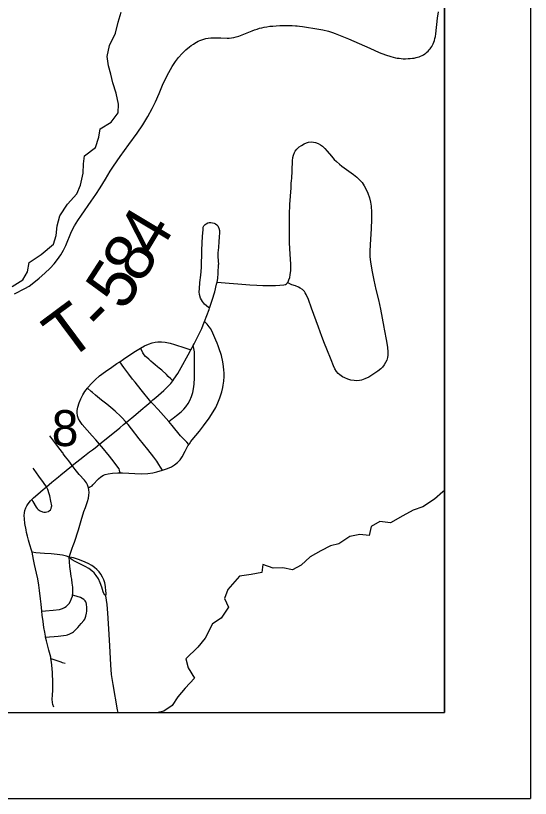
# Model space of a CAD drawing. Extents: x -14196 to 143, y -6096 to 28.
# Drawn here: x 64.404 to 65.003, y 16.799 to 17.71 of the extents above; entities that cross this region are included whole.
import ezdxf

# ---------------------------------------------------------------- set-up
doc = ezdxf.new("R2010")
doc.units = 0
for name, color, linetype in [('GM_X_Corporation', 7, 'Continuous'), ('GM_X_Major_River', 7, 'Continuous'), ('GM_X_Minor_River', 7, 'Continuous'), ('GM_X_Section_Text', 7, 'Continuous'), ('GM_X_Township_Road', 7, 'Continuous'), ('GM_X_Township_Road_Text', 7, 'Continuous'), ('SH_Data', 7, 'Continuous')]:
    doc.layers.add(name, color=color, linetype=linetype)

msp = doc.modelspace()

# ---------------------------------------------------------------- linework, layer by layer
at = {"layer": 'GM_X_Corporation'}
for points in [[(58.10282, 16.89854), (64.90282, 16.89854), (64.90282, 18.72858), (64.42664, 18.73471), (64.36963, 18.73435), (63.68786, 18.74138), (63.08865, 18.75772), (62.54026, 18.77306)], [(62.31172, 16.89854), (64.90282, 16.89854), (64.90282, 18.72858), (64.42664, 18.73471), (64.36963, 18.73435), (63.68786, 18.74138), (63.08865, 18.75772), (62.54026, 18.77306)]]:
    msp.add_lwpolyline(points, dxfattribs=at)
msp.add_lwpolyline([(64.36791, 16.89854), (64.90282, 16.89854), (64.90282, 17.75358), (64.39395, 17.76746)], close=True, dxfattribs=at)
at = {"layer": 'GM_X_Major_River'}
msp.add_lwpolyline([(64.90282, 17.15681), (64.90109, 17.15543), (64.89132, 17.147), (64.87777, 17.13777), (64.86644, 17.13387), (64.85437, 17.12731), (64.84005, 17.11922), (64.82752, 17.12099), (64.81773, 17.11483), (64.81518, 17.10457), (64.80455, 17.10561), (64.79283, 17.10322), (64.78003, 17.09476), (64.77019, 17.09239), (64.75888, 17.0866), (64.74644, 17.07966), (64.73631, 17.07009), (64.72613, 17.06468), (64.71473, 17.06685), (64.70336, 17.06636), (64.69156, 17.07079), (64.69052, 17.06131), (64.67803, 17.0593), (64.66441, 17.05727), (64.65092, 17.04161), (64.64686, 17.03134), (64.65152, 17.02115), (64.64294, 17.00819), (64.63277, 17.00165), (64.62461, 16.98491), (64.616, 16.97459), (64.60174, 16.96082), (64.6045, 16.95062), (64.61184, 16.93857), (64.60097, 16.92673), (64.59273, 16.9168), (64.58602, 16.90651), (64.57623, 16.89998), (64.56973, 16.89854)], dxfattribs=at)
at = {"layer": 'GM_X_Minor_River'}
msp.add_lwpolyline([(64.4, 17.39441), (64.41243, 17.40211), (64.41764, 17.41165), (64.41942, 17.42229), (64.43373, 17.43153), (64.44801, 17.44381), (64.45094, 17.4537), (64.45234, 17.4651), (64.45525, 17.47651), (64.4642, 17.49026), (64.47507, 17.5025), (64.47952, 17.51241), (64.48241, 17.52648), (64.48267, 17.53711), (64.48409, 17.54661), (64.49688, 17.55623), (64.50055, 17.56841), (64.50234, 17.57791), (64.51516, 17.58563), (64.523, 17.59671), (64.52366, 17.60659), (64.52087, 17.61947), (64.51695, 17.63158), (64.51457, 17.64181), (64.51182, 17.65127), (64.51019, 17.66226), (64.51309, 17.67482), (64.52014, 17.68932), (64.52304, 17.70225), (64.52672, 17.71368)], dxfattribs=at)
at = {"layer": 'GM_X_Township_Road'}
for points in [[(64.40255, 17.38586), (64.4147, 17.3921), (64.4195, 17.39495), (64.42506, 17.39891), (64.43132, 17.40401), (64.4378, 17.40981), (64.44396, 17.41594), (64.44856, 17.42098), (64.45247, 17.4258), (64.45442, 17.42848), (64.45644, 17.43136), (64.45803, 17.43382), (64.45962, 17.43669), (64.46233, 17.44227), (64.46906, 17.4583), (64.47243, 17.46494), (64.47627, 17.47132), (64.48042, 17.47749), (64.49183, 17.4937), (64.4971, 17.50137), (64.50211, 17.50922), (64.50825, 17.51929), (64.51398, 17.52889), (64.51769, 17.53462), (64.52549, 17.54584), (64.53572, 17.55992), (64.54517, 17.57301), (64.5518, 17.58278), (64.55766, 17.5923), (64.56274, 17.60155), (64.56658, 17.60936), (64.57079, 17.61903), (64.57488, 17.62873), (64.57872, 17.63715), (64.58211, 17.6437), (64.58613, 17.65058), (64.58985, 17.65619), (64.59356, 17.66104), (64.59758, 17.66567), (64.60196, 17.66998), (64.60622, 17.67353), (64.60831, 17.67507), (64.61076, 17.67672), (64.61256, 17.67785), (64.61448, 17.67889), (64.61632, 17.67988), (64.61837, 17.68074), (64.62052, 17.68161), (64.6228, 17.68235), (64.62532, 17.68297), (64.62781, 17.68344), (64.63085, 17.68383), (64.63291, 17.68402), (64.63515, 17.6841), (64.6387, 17.68402), (64.64254, 17.68384), (64.64994, 17.6836), (64.65239, 17.68366), (64.65498, 17.68389), (64.65788, 17.68431), (64.66065, 17.685), (64.66378, 17.686), (64.66737, 17.6874), (64.67119, 17.68896), (64.67508, 17.69055), (64.67915, 17.69221), (64.68198, 17.69326), (64.68498, 17.69419), (64.68759, 17.69499), (64.69032, 17.69565), (64.69327, 17.69628), (64.69637, 17.69686), (64.69968, 17.69733), (64.7031, 17.6977), (64.70702, 17.69801), (64.71112, 17.69818), (64.72098, 17.6983), (64.72557, 17.69826), (64.72941, 17.69805), (64.73161, 17.69789), (64.73408, 17.69764), (64.73784, 17.69715), (64.74234, 17.69641), (64.75218, 17.69482), (64.76127, 17.69311), (64.76789, 17.69151), (64.77015, 17.69092), (64.77263, 17.69011), (64.77588, 17.68901), (64.77965, 17.6876), (64.79117, 17.68295), (64.80368, 17.67747), (64.81615, 17.67186), (64.82692, 17.66702), (64.83443, 17.66406), (64.84033, 17.66213), (64.84575, 17.66079), (64.84787, 17.66038), (64.85004, 17.66007), (64.85262, 17.65983), (64.85499, 17.65966), (64.85773, 17.65958), (64.86058, 17.65968), (64.86315, 17.65989), (64.86555, 17.66013), (64.86766, 17.66044), (64.86982, 17.66095), (64.87148, 17.66137), (64.87326, 17.66192), (64.87505, 17.6626), (64.87681, 17.66347), (64.87845, 17.66432), (64.88001, 17.66538), (64.88124, 17.66626), (64.88247, 17.66727), (64.88381, 17.66852), (64.88512, 17.66989), (64.8861, 17.67098), (64.8871, 17.67228), (64.88813, 17.67376), (64.88908, 17.67543), (64.88985, 17.67709), (64.89054, 17.67885), (64.89124, 17.68082), (64.89174, 17.68301), (64.89228, 17.68567), (64.89273, 17.68851), (64.89491, 17.70695), (64.89584, 17.7143)], [(64.7203, 17.39897), (64.72084, 17.39976), (64.72187, 17.40201), (64.72276, 17.40499), (64.7234, 17.40802), (64.72393, 17.41297), (64.72405, 17.42042), (64.72347, 17.43221), (64.72273, 17.44522), (64.72251, 17.45392), (64.72244, 17.46573), (64.72256, 17.47814), (64.72306, 17.48992), (64.72432, 17.50912), (64.72449, 17.51097), (64.72448, 17.51223), (64.72466, 17.51407), (64.72491, 17.51841), (64.72509, 17.51963), (64.72559, 17.52956), (64.72593, 17.54073), (64.72637, 17.54443), (64.7271, 17.54743), (64.72821, 17.55033), (64.72914, 17.55194), (64.73111, 17.55434), (64.73382, 17.55689), (64.73633, 17.55872), (64.73958, 17.56054), (64.74247, 17.56169), (64.74486, 17.56232), (64.74796, 17.56267), (64.75043, 17.56252), (64.75285, 17.56206), (64.75576, 17.56098), (64.75845, 17.55946), (64.76095, 17.55762), (64.76368, 17.55507), (64.76657, 17.55181), (64.77131, 17.54603), (64.77466, 17.54236), (64.77732, 17.53977), (64.78065, 17.53696), (64.78354, 17.53462), (64.78906, 17.53058), (64.79718, 17.52483), (64.80104, 17.5217), (64.80456, 17.5182), (64.80696, 17.51535), (64.80944, 17.51177), (64.81188, 17.50745), (64.81387, 17.5029), (64.81558, 17.49757), (64.81673, 17.49274), (64.8175, 17.48783), (64.81802, 17.48101), (64.8181, 17.47293), (64.81773, 17.46175), (64.81637, 17.44315), (64.81609, 17.43508), (64.81623, 17.42949), (64.81687, 17.42269), (64.81869, 17.41166), (64.82063, 17.40191), (64.82315, 17.39101), (64.82615, 17.37895), (64.82848, 17.36801), (64.8324, 17.34724), (64.83273, 17.34479), (64.83529, 17.33072), (64.83656, 17.32337), (64.837, 17.31841), (64.8369, 17.31468), (64.83649, 17.31161), (64.83565, 17.30862), (64.83441, 17.30578), (64.8328, 17.30312), (64.83088, 17.30069), (64.82869, 17.29849), (64.8253, 17.29577), (64.8197, 17.29183), (64.81491, 17.28893), (64.81041, 17.28684), (64.80628, 17.28546), (64.80386, 17.28497), (64.80078, 17.28468), (64.79769, 17.28482), (64.79402, 17.28546), (64.79045, 17.28655), (64.78702, 17.288), (64.78426, 17.28945), (64.78119, 17.29158), (64.77935, 17.29322), (64.77727, 17.29552), (64.77532, 17.29868), (64.77379, 17.30207), (64.77099, 17.30897), (64.76593, 17.32161), (64.76337, 17.32793), (64.76029, 17.33606), (64.75619, 17.34713), (64.75082, 17.3617), (64.74803, 17.36926), (64.74452, 17.3792), (64.74214, 17.38494), (64.74094, 17.38711), (64.73987, 17.38862), (64.73765, 17.39077), (64.73511, 17.39257), (64.73293, 17.39374), (64.72944, 17.39502), (64.72531, 17.39638), (64.72308, 17.39746), (64.7203, 17.39897)], [(64.62943, 17.36909), (64.62848, 17.36982), (64.62587, 17.37183), (64.62372, 17.37385), (64.62122, 17.37708), (64.61917, 17.38096), (64.61785, 17.38506), (64.61763, 17.38806), (64.61778, 17.39166), (64.61822, 17.39906), (64.61939, 17.40763), (64.62005, 17.41664), (64.62071, 17.43649), (64.62086, 17.44543), (64.62115, 17.45254), (64.62204, 17.46092), (64.62201, 17.46213), (64.62225, 17.46335), (64.62305, 17.46501), (64.62426, 17.46642), (64.62575, 17.46756), (64.62743, 17.46837), (64.62923, 17.4688), (64.63108, 17.46891), (64.63294, 17.46869), (64.63473, 17.46816), (64.63642, 17.46738), (64.63789, 17.46627), (64.6391, 17.46488), (64.64003, 17.4633), (64.6405, 17.46216), (64.64095, 17.45975), (64.64101, 17.45724), (64.64053, 17.45167), (64.64018, 17.44671), (64.63976, 17.43992), (64.63943, 17.43684), (64.63917, 17.43376), (64.63915, 17.42882), (64.63976, 17.42023)], [(64.63824, 17.39955), (64.63904, 17.40361), (64.63956, 17.40997), (64.63976, 17.42023)], [(64.62943, 17.36909), (64.63276, 17.3787), (64.63553, 17.38824), (64.6378, 17.39728), (64.63824, 17.39955)], [(64.63824, 17.39955), (64.64309, 17.39912), (64.65237, 17.39829), (64.66226, 17.39744), (64.67647, 17.39633), (64.68452, 17.39586), (64.69135, 17.39563), (64.6988, 17.3955), (64.7062, 17.39565), (64.71149, 17.39583), (64.71581, 17.3962), (64.71784, 17.39682), (64.71892, 17.39735), (64.7198, 17.39824), (64.7203, 17.39897)], [(64.62364, 17.35376), (64.6289, 17.36756), (64.62943, 17.36909)], [(64.60547, 17.21045), (64.60601, 17.21133), (64.6078, 17.21386), (64.60929, 17.21583), (64.61765, 17.22582), (64.62262, 17.23219), (64.62914, 17.24126), (64.63392, 17.24852), (64.63665, 17.25341), (64.63932, 17.25902), (64.64157, 17.26482), (64.64379, 17.27194), (64.64492, 17.27674), (64.6454, 17.27975), (64.64599, 17.28404), (64.64638, 17.2896), (64.64656, 17.29392), (64.64631, 17.29699), (64.64592, 17.3013), (64.64504, 17.30682), (64.64347, 17.31409), (64.64267, 17.31643), (64.64128, 17.32054), (64.63964, 17.32522), (64.63822, 17.32865), (64.63686, 17.33211), (64.6334, 17.34008), (64.63083, 17.34503), (64.62917, 17.34764), (64.62664, 17.35048), (64.62364, 17.35376)], [(64.61057, 17.32578), (64.61165, 17.32777), (64.61668, 17.33771), (64.62035, 17.34558), (64.62337, 17.35306), (64.62364, 17.35376)], [(64.52501, 17.30688), (64.52945, 17.30995), (64.53669, 17.31477), (64.5435, 17.31897), (64.54913, 17.32264)], [(64.54913, 17.32264), (64.55399, 17.32534), (64.55852, 17.32737), (64.56265, 17.32875), (64.56629, 17.32957), (64.56936, 17.32997), (64.57371, 17.33), (64.57804, 17.32954), (64.58356, 17.32857), (64.58891, 17.32688), (64.6006, 17.32283), (64.60296, 17.32209), (64.60775, 17.32057)], [(64.58671, 17.28471), (64.58466, 17.28674), (64.58153, 17.28983), (64.5794, 17.29194), (64.5738, 17.29685), (64.57092, 17.2992), (64.56907, 17.30082), (64.56619, 17.30317), (64.56385, 17.30519), (64.56101, 17.30757), (64.55876, 17.30968), (64.55643, 17.3117), (64.55513, 17.31311), (64.55356, 17.31486), (64.55177, 17.31736), (64.54978, 17.32132), (64.54913, 17.32264)], [(64.58213, 17.23713), (64.58593, 17.24029), (64.58718, 17.24133), (64.59107, 17.24437), (64.5964, 17.24869), (64.59956, 17.25169), (64.602, 17.25449), (64.60448, 17.25805), (64.60657, 17.26185), (64.60852, 17.26639), (64.61001, 17.27112), (64.61087, 17.27536), (64.6115, 17.2809), (64.61186, 17.28829), (64.6119, 17.29386), (64.61192, 17.29632), (64.61183, 17.30066), (64.61185, 17.30374), (64.61186, 17.30931), (64.61183, 17.31425), (64.61192, 17.31602), (64.61182, 17.31845), (64.61133, 17.3222), (64.61057, 17.32578)], [(64.60775, 17.32057), (64.60929, 17.32341), (64.61057, 17.32578)], [(64.58671, 17.28471), (64.58807, 17.28648), (64.59258, 17.29313), (64.59667, 17.30004), (64.60458, 17.3147), (64.60775, 17.32057)], [(64.48731, 17.276), (64.48794, 17.27684), (64.49244, 17.28197), (64.49643, 17.28587), (64.5016, 17.29028), (64.50853, 17.29547), (64.51564, 17.30042), (64.52179, 17.30464), (64.52501, 17.30688)], [(64.56125, 17.26029), (64.54995, 17.27424), (64.54283, 17.28307), (64.53995, 17.28665), (64.53551, 17.29256), (64.52972, 17.30027), (64.52501, 17.30688)], [(64.56125, 17.26029), (64.5635, 17.26231), (64.56685, 17.26506), (64.57616, 17.27317), (64.58059, 17.27745), (64.5843, 17.28158), (64.58671, 17.28471)], [(64.50141, 17.21082), (64.49702, 17.21583), (64.49297, 17.2204), (64.48695, 17.22723), (64.48148, 17.23382), (64.47901, 17.23734), (64.4771, 17.2405), (64.47588, 17.24398), (64.47553, 17.24766), (64.47565, 17.25011), (64.47628, 17.25379), (64.47785, 17.25917), (64.47968, 17.26378), (64.48193, 17.2682), (64.48458, 17.27238), (64.48731, 17.276)], [(64.53267, 17.23628), (64.53172, 17.23742), (64.52794, 17.24153), (64.5262, 17.24327), (64.5198, 17.24911), (64.51471, 17.25358), (64.5099, 17.25739), (64.5036, 17.26229), (64.49696, 17.26778), (64.49335, 17.271), (64.49195, 17.27215), (64.48731, 17.276)], [(64.53267, 17.23628), (64.54383, 17.24542), (64.55238, 17.25259), (64.55424, 17.25418), (64.56125, 17.26029)], [(64.58213, 17.23713), (64.56985, 17.25126), (64.5639, 17.25729), (64.56125, 17.26029)], [(64.50141, 17.21082), (64.52514, 17.23008), (64.52944, 17.23363), (64.53267, 17.23628)], [(64.57483, 17.18045), (64.57244, 17.18414), (64.57045, 17.18722), (64.56818, 17.1909), (64.5646, 17.19588), (64.55776, 17.20455), (64.54774, 17.21701), (64.53877, 17.22879), (64.5349, 17.23361), (64.53267, 17.23628)], [(64.60547, 17.21045), (64.60291, 17.21302), (64.59943, 17.2165), (64.59583, 17.22071), (64.58619, 17.23247), (64.58213, 17.23713)], [(64.46984, 17.18599), (64.46563, 17.1913), (64.4619, 17.19625), (64.45936, 17.19975), (64.45905, 17.20029), (64.4583, 17.20127), (64.45306, 17.20817), (64.44713, 17.21609), (64.44385, 17.22058)], [(64.46984, 17.18599), (64.48403, 17.19739), (64.48998, 17.20186), (64.49348, 17.20443), (64.49635, 17.20677), (64.50141, 17.21082)], [(64.52558, 17.17754), (64.52525, 17.17876), (64.52479, 17.18043), (64.52415, 17.18209), (64.52292, 17.18416), (64.51836, 17.1901), (64.5157, 17.19348), (64.51301, 17.19677), (64.50405, 17.20774), (64.50141, 17.21082)], [(64.57483, 17.18045), (64.58064, 17.18258), (64.58514, 17.18466), (64.58885, 17.1869), (64.5923, 17.18948), (64.59524, 17.19262), (64.59767, 17.19618), (64.60114, 17.20273), (64.6043, 17.20875), (64.60471, 17.20922), (64.60547, 17.21045)], [(64.43977, 17.16125), (64.44593, 17.16653), (64.45357, 17.1729), (64.45644, 17.17527), (64.46903, 17.18534), (64.46984, 17.18599)], [(64.4886, 17.16016), (64.48832, 17.16138), (64.48736, 17.16365), (64.48617, 17.16581), (64.48396, 17.16881), (64.47779, 17.17572), (64.47323, 17.18151), (64.46984, 17.18599)], [(64.43977, 17.16125), (64.4362, 17.16621), (64.43081, 17.17372), (64.42534, 17.18132), (64.42439, 17.18288)], [(64.4886, 17.16016), (64.48993, 17.16085), (64.49142, 17.16157), (64.49282, 17.16252), (64.49379, 17.16352), (64.50017, 17.17053), (64.503, 17.17294), (64.5062, 17.17479), (64.50792, 17.17546), (64.51151, 17.17643), (64.51644, 17.17713), (64.52264, 17.17754), (64.52558, 17.17754)], [(64.52558, 17.17754), (64.5282, 17.17755), (64.53561, 17.17717), (64.54239, 17.17675), (64.54983, 17.17649), (64.55789, 17.17677), (64.56343, 17.17748), (64.56828, 17.17854), (64.57483, 17.18045)], [(64.42271, 17.14633), (64.42473, 17.14833), (64.42985, 17.15284), (64.43603, 17.15805), (64.43977, 17.16125)], [(64.42271, 17.14633), (64.42395, 17.14415), (64.42772, 17.13751), (64.4289, 17.13602), (64.4302, 17.13493), (64.43248, 17.13324), (64.43504, 17.13226), (64.43676, 17.1318), (64.43853, 17.13167), (64.44032, 17.13191), (64.442, 17.13255), (64.44301, 17.13324), (64.44431, 17.13455), (64.44524, 17.13614), (64.44579, 17.13788), (64.44585, 17.13909), (64.44561, 17.14091), (64.44531, 17.14272), (64.44489, 17.14452), (64.44352, 17.15055), (64.44304, 17.15293), (64.44132, 17.15795), (64.43977, 17.16125)], [(64.46597, 17.07942), (64.46974, 17.08991), (64.4708, 17.09285), (64.47234, 17.09691), (64.47684, 17.11113), (64.48019, 17.12182), (64.48336, 17.13256), (64.48499, 17.13725), (64.48752, 17.14428), (64.48851, 17.14789), (64.48914, 17.15156), (64.48933, 17.15466), (64.48916, 17.15775), (64.4886, 17.16016)], [(64.42304, 17.08495), (64.42278, 17.08612), (64.42251, 17.08733), (64.42058, 17.0938), (64.41894, 17.09906), (64.4184, 17.1008), (64.41811, 17.10202), (64.41762, 17.10379), (64.41668, 17.10802), (64.41607, 17.11107), (64.41475, 17.11841), (64.41399, 17.12395), (64.41384, 17.12767), (64.41405, 17.13076), (64.41466, 17.13379), (64.41567, 17.13671), (64.41677, 17.13892), (64.41846, 17.1415), (64.42122, 17.14484), (64.42271, 17.14633)], [(64.46597, 17.07942), (64.46301, 17.08057), (64.45833, 17.08154), (64.45217, 17.08234), (64.44528, 17.08304), (64.43727, 17.08364), (64.42742, 17.08455), (64.42304, 17.08495)], [(64.43432, 17.01631), (64.43349, 17.02463), (64.43274, 17.03079), (64.43156, 17.04065), (64.43074, 17.04679), (64.42957, 17.0541), (64.42819, 17.06076), (64.42575, 17.07097), (64.42468, 17.07642), (64.42399, 17.08069), (64.42304, 17.08495)], [(64.50879, 17.03438), (64.50907, 17.03628), (64.50912, 17.03788), (64.50902, 17.03986), (64.50836, 17.04502), (64.50754, 17.04925), (64.50649, 17.0528), (64.50502, 17.05618), (64.50313, 17.05935), (64.50089, 17.06229), (64.49836, 17.06497), (64.49555, 17.06736), (64.4925, 17.06944), (64.48818, 17.07182), (64.48206, 17.07468), (64.4769, 17.07673), (64.47139, 17.07863), (64.46894, 17.07908), (64.46597, 17.07942)], [(64.50879, 17.03438), (64.50747, 17.03557), (64.50654, 17.03695), (64.50559, 17.03892), (64.50413, 17.0443), (64.50239, 17.04959), (64.50028, 17.05405), (64.49755, 17.05814), (64.4951, 17.06091), (64.49237, 17.0634), (64.48893, 17.06599), (64.48471, 17.06857), (64.48085, 17.07051), (64.4763, 17.07264), (64.47305, 17.0744), (64.46968, 17.07635), (64.46803, 17.07754), (64.46597, 17.07942)], [(64.47014, 17.03524), (64.47044, 17.03709), (64.47058, 17.04019), (64.47037, 17.04391), (64.47005, 17.04698), (64.46981, 17.04881), (64.46908, 17.05372), (64.46868, 17.0568), (64.46812, 17.06048), (64.46709, 17.06849), (64.46597, 17.07942)], [(64.43432, 17.01631), (64.43878, 17.0167), (64.44741, 17.01746), (64.45483, 17.01846), (64.45842, 17.01949), (64.46065, 17.02058), (64.46269, 17.02198), (64.46453, 17.02365), (64.46613, 17.02556), (64.46778, 17.0282), (64.46905, 17.03104), (64.46994, 17.03403), (64.47014, 17.03524)], [(64.43879, 16.98606), (64.44324, 16.98649), (64.44856, 16.98697), (64.45335, 16.9874), (64.46277, 16.98869), (64.46414, 16.989), (64.46711, 16.99), (64.47004, 16.99169), (64.4711, 16.99253), (64.47298, 16.99441), (64.47612, 16.99737), (64.48023, 17.00208), (64.48337, 17.00577), (64.48427, 17.00728), (64.48567, 17.01072), (64.48651, 17.01398), (64.48687, 17.01664), (64.48675, 17.02075), (64.48645, 17.02467), (64.48585, 17.02637), (64.48549, 17.02732), (64.4848, 17.02846), (64.48312, 17.03017), (64.48137, 17.03132), (64.4792, 17.03223), (64.47545, 17.03344), (64.47152, 17.03477), (64.47014, 17.03524)], [(64.52304, 16.89854), (64.52259, 16.90143), (64.51717, 16.9312), (64.51548, 16.94284), (64.51458, 16.95395), (64.5134, 16.97612), (64.51241, 16.99581), (64.5112, 17.01425), (64.51019, 17.02403), (64.50879, 17.03438)], [(64.43879, 16.98606), (64.43855, 16.98716), (64.43771, 16.99203), (64.43687, 16.99754), (64.43591, 17.0043), (64.43478, 17.01166), (64.43432, 17.01631)], [(64.44489, 16.96124), (64.44464, 16.96272), (64.44256, 16.97106), (64.43973, 16.98175), (64.43879, 16.98606)], [(64.44489, 16.96124), (64.44833, 16.96005), (64.45294, 16.95844), (64.45644, 16.95739), (64.45813, 16.9568), (64.46159, 16.95603)], [(64.44841, 16.90484), (64.44732, 16.90775), (64.44674, 16.91017), (64.44644, 16.91385), (64.44658, 16.91881), (64.44705, 16.92438), (64.44709, 16.93307), (64.44665, 16.94487), (64.44602, 16.95354), (64.44557, 16.95723), (64.44489, 16.96124)]]:
    msp.add_lwpolyline(points, dxfattribs=at)
at = {"layer": 'SH_Data'}
for p, q in [((65.00282, 23.79854), (65.00282, 16.79854)), ((64.90282, 23.69854), (64.90282, 16.89854)), ((58.10282, 16.89854), (64.90282, 16.89854)), ((58.00282, 16.79854), (65.00282, 16.79854))]:
    msp.add_line(p, q, dxfattribs=at)

# ---------------------------------------------------------------- texts
at = {"layer": 'GM_X_Section_Text'}
msp.add_text('8', height=0.04186, rotation=0.00001, dxfattribs=at).set_placement((64.44582, 17.20862))
at = {"layer": 'GM_X_Township_Road_Text'}
for s, rotation, p in [('4', 59.0648, (64.56781, 17.4262)), ('8', 59.60032, (64.55018, 17.39613)), ('5', 57.12309, (64.52977, 17.36445)), ('T', 36.67361, (64.46426, 17.30641)), ('-', 45.36787, (64.50544, 17.33795))]:
    msp.add_text(s, height=0.05682, rotation=rotation, dxfattribs=at).set_placement(p)

doc.saveas('drawing.dxf')
